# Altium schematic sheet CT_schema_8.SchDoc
size 405 x 220 mm
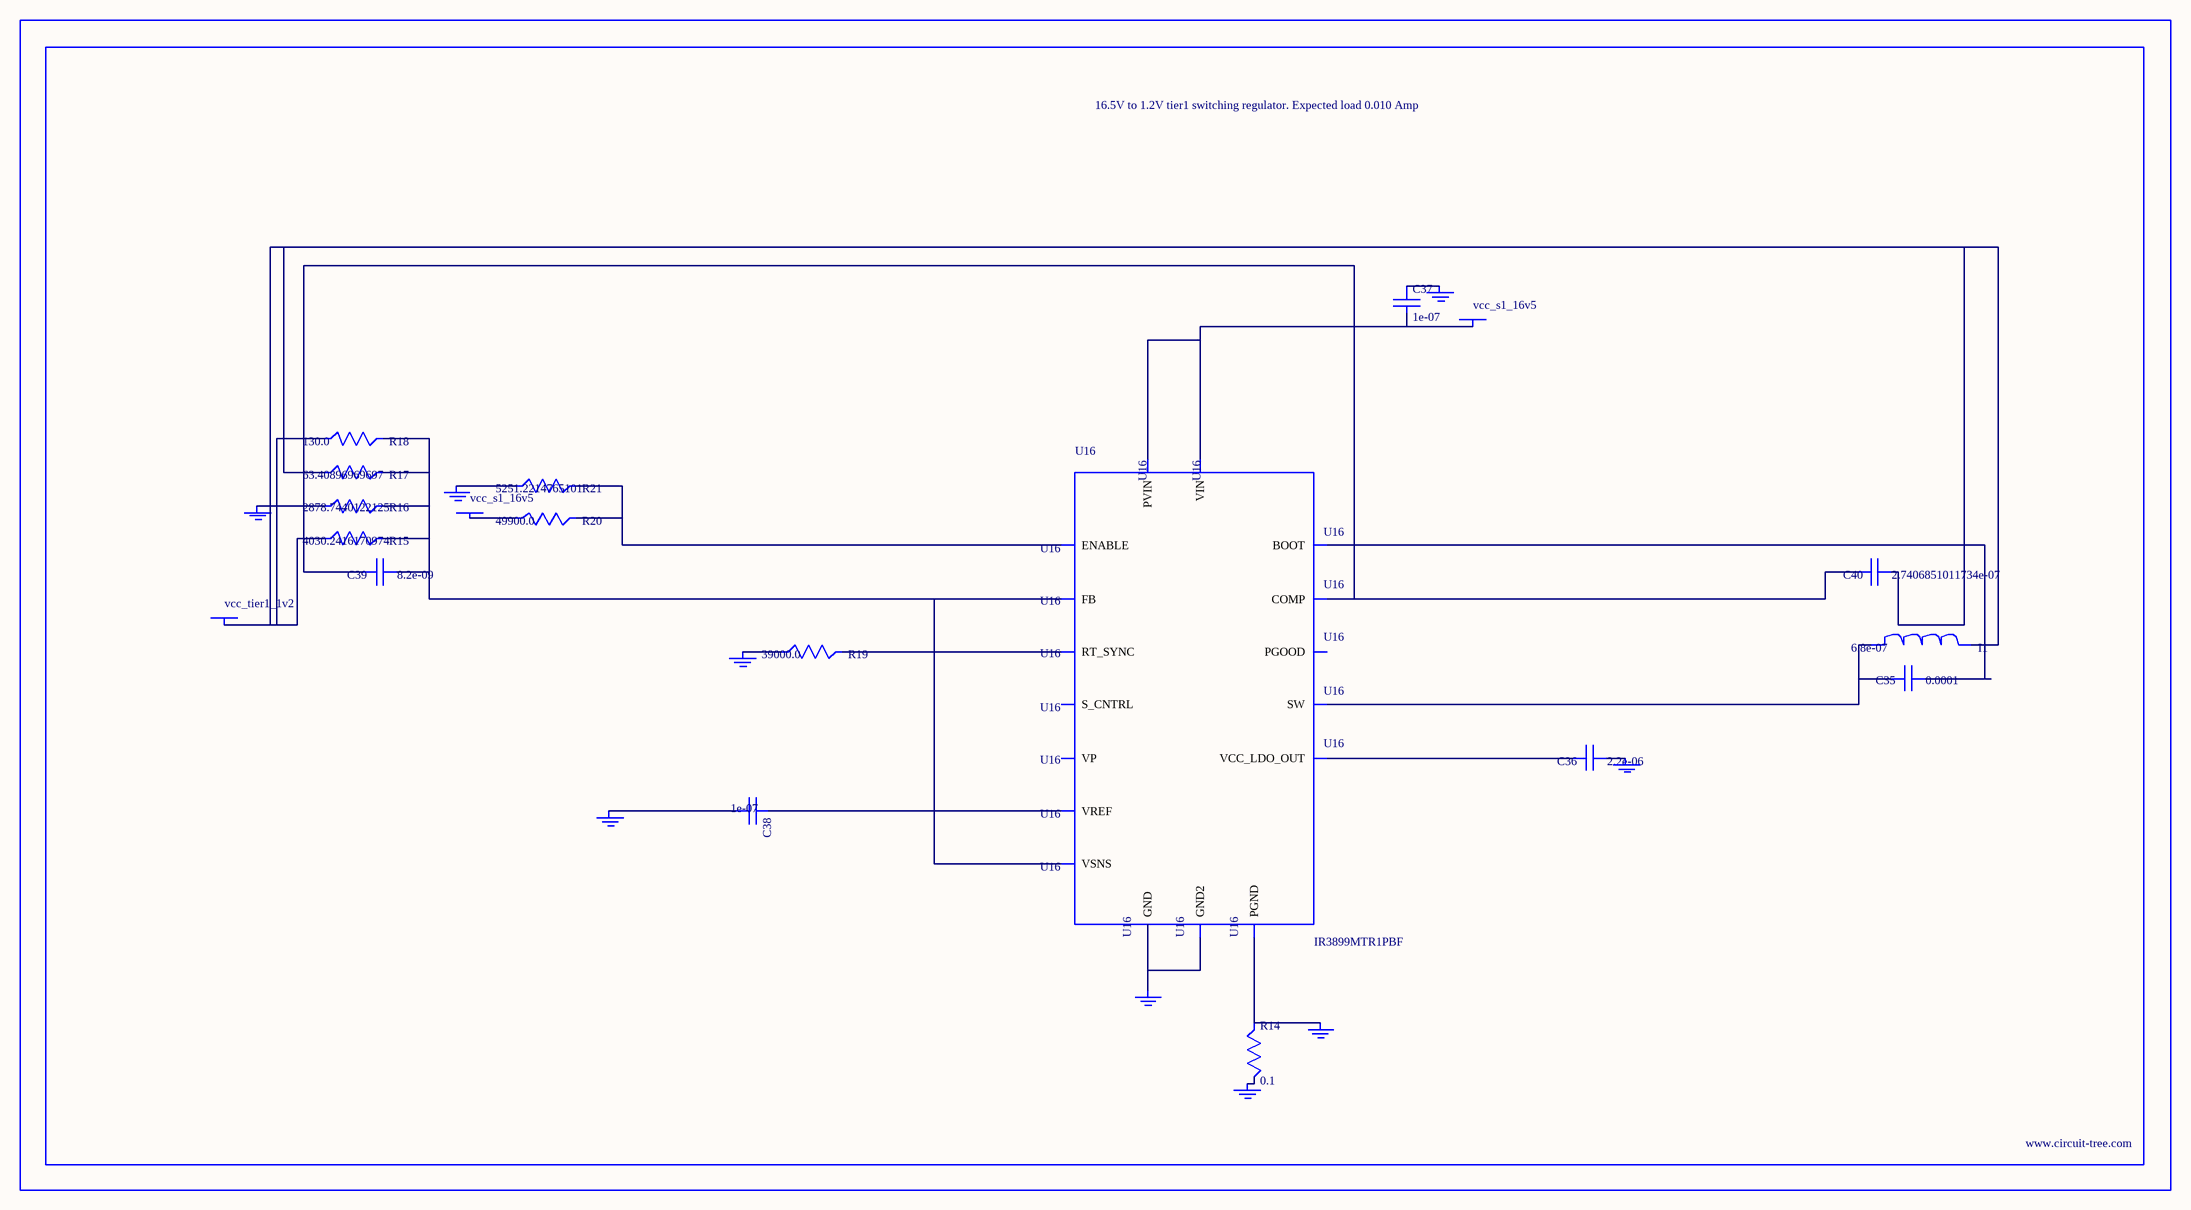
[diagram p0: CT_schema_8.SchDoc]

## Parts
BORDER7  (no value)
C35  0.0001  [C1210]
C36  2.2e-06  [C0603]
C37  1e-07  [C0402]
C38  1e-07  [C0402]
C39  8.2e-09  [C0402]
C40  2.7406851011734e-07  [R0603]
GND_INSTANCE_7_0  (no value)
GND_INSTANCE_7_1  (no value)
GND_INSTANCE_7_2  (no value)
GND_INSTANCE_7_3  (no value)
GND_INSTANCE_7_4  (no value)
GND_INSTANCE_7_5  (no value)
GND_INSTANCE_7_6  (no value)
GND_INSTANCE_7_7  (no value)
GND_INSTANCE_7_8  (no value)
I1  6.8e-07  [IND25X25CZ]
POWER_INSTANCE_7_0  vcc_s1_16v5
POWER_INSTANCE_7_1  vcc_s1_16v5
POWER_INSTANCE_7_2  vcc_tier1_1v2
R14  0.1  [R0603]
R15  4030.2416170974  [R0603]
R16  2878.7440122125  [R0603]
R17  63.40896969697  [R0603]
R18  130.0  [R0603]
R19  39000.0  [R0603]
R20  49900.0  [R0603]
R21  5251.2214765101  [R0603]
U16  IR3899MTR1PBF  [IR3899MTR1PBF]

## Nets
NetC35_1: C35.1 U16.14(BOOT)
NetC35_2: C35.2 I1.1 U16.12(SW)
NetC36_1: C36.1 GND_INSTANCE_7_4.0(GND)
NetC36_2: C36.2 U16.10(VCC_LDO_OUT)
NetC37_1: C37.1 GND_INSTANCE_7_3.0(GND)
NetC37_2: C37.2 POWER_INSTANCE_7_0.0(PWR) U16.9(VIN) U16.13(PVIN)
NetC38_1: C38.1 U16.2(VREF)
NetC38_2: C38.2 GND_INSTANCE_7_1.0(GND)
NetC39_1: C39.1 R15.2 R16.2 R17.2 R18.2 U16.1(FB) U16.8(VSNS)
NetC39_2: C39.2 C40.2 U16.3(COMP)
NetC40_1: C40.1 I1.2 POWER_INSTANCE_7_2.0(PWR) R15.1 R17.1 R18.1
NetGND_INSTANCE_7_0_0: GND_INSTANCE_7_0.0(GND) R16.1
NetGND_INSTANCE_7_2_0: GND_INSTANCE_7_2.0(GND) R19.1
NetGND_INSTANCE_7_5_0: GND_INSTANCE_7_5.0(GND) R14.2
NetGND_INSTANCE_7_6_0: GND_INSTANCE_7_6.0(GND) R14.1 U16.11(PGND)
NetGND_INSTANCE_7_7_0: GND_INSTANCE_7_7.0(GND) R21.1
NetGND_INSTANCE_7_8_0: GND_INSTANCE_7_8.0(GND) U16.4(GND) U16.17(GND2)
NetPOWER_INSTANCE_7_1_0: POWER_INSTANCE_7_1.0(PWR) R20.1
NetR19_2: R19.2 U16.5(RT_SYNC)
NetR20_2: R20.2 R21.2 U16.15(ENABLE)

Not connected (* = marked no-connect by the designer): U16 6(S_CNTRL) 7(PGOOD) 16(VP)

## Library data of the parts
BORDER7 = BORDER_PAGE7
C35 = GRM32ER61A107ME20L
C36 = C0603C225K8RACTU
C37 C38 = C0402C104K3RACTU
C39 = C0402C822K3RAC
C40 = C40
GND_INSTANCE_7_0-GND_INSTANCE_7_8 = GND
I1 = IHLP2525CZERR68M01
POWER_INSTANCE_7_0-POWER_INSTANCE_7_2 = PWR
R14 = ERJ-3RSFR10V
R15 = R15
R16 = R16
R17 = R17
R18 = RC0603JR-07130RL
R19 = RC0603JR-0739KL
R20 = RC0603FR-0749K9
R21 = R21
